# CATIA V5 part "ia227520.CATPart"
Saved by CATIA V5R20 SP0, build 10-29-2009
Part number: IA 227520
Revision: ANY
Definition: UNKNOWN
Nomenclature: IA 227520
Source: Unknown
Bounding box of the stored display mesh (mm): x -1.102 to 1.102, y -7.751 to 0, z -1.102 to 1.102
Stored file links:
  C:\Users\Utente\Desktop\IO LAVORO\3D X SITO CF\CUMSA\3D files IA\IA 227520\ia227520.CATPart
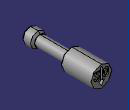
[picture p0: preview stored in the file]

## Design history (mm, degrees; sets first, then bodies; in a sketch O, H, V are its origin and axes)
Body1 "Cortar-Extruir3" (main body)
  Solid1: solid without history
